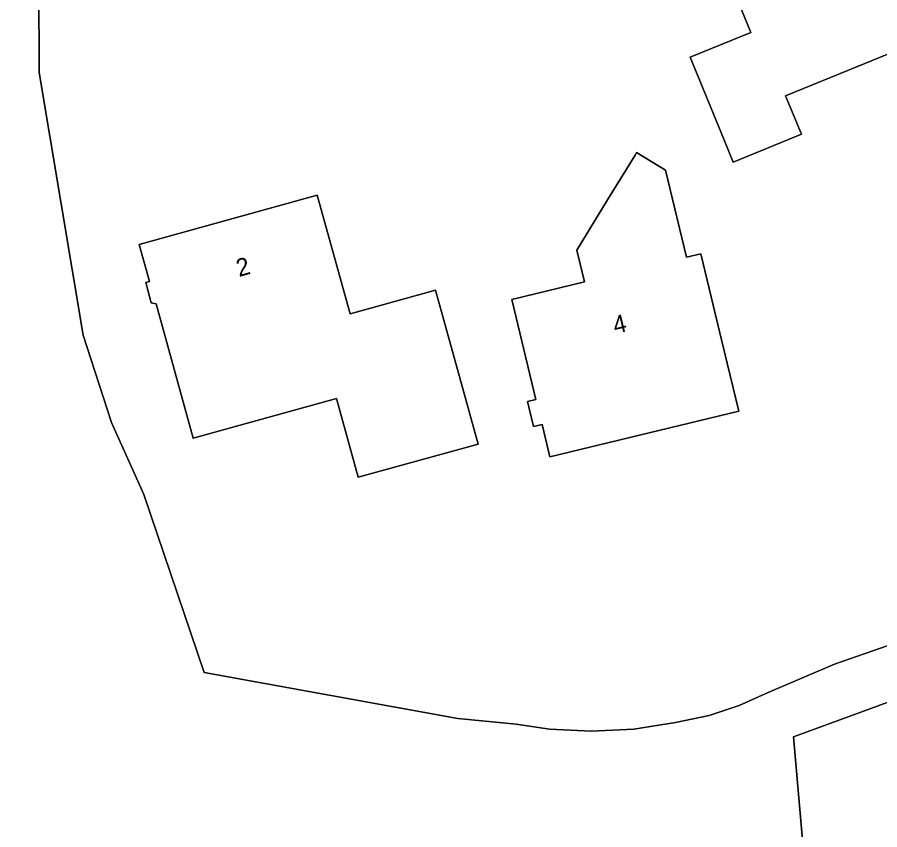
# Model space of a CAD drawing. Extents: x 162156 to 163172, y 378995 to 380779.
# Drawn here: x 162663.78 to 162712.54, y 380088.42 to 380134.38 of the extents above; entities that cross this region are included whole.
import ezdxf

# ---------------------------------------------------------------- set-up
doc = ezdxf.new("R2010")
doc.units = 0
for name, color, linetype in [('IMGEO_Erf', 7, 'Continuous'), ('IMGEO_Naaldbos', 7, 'Continuous'), ('IMGEO_Pand', 7, 'Continuous'), ('IMGEO_Pand_nummerreeks', 7, 'Continuous')]:
    doc.layers.add(name, color=color, linetype=linetype)

msp = doc.modelspace()

# ---------------------------------------------------------------- linework, layer by layer
at = {"layer": 'IMGEO_Erf'}
for points in [[(162714.758, 380133.013), (162707.223, 380129.931), (162708.11, 380127.761), (162704.256, 380126.184), (162703.725, 380127.483), (162701.832, 380132.11), (162705.263, 380133.513), (162704.065, 380136.442), (162715.035, 380140.929)], [(162666.225, 380138.522), (162664.994, 380136.169), (162665.017, 380131.245), (162667.515, 380116.396), (162669.104, 380111.454), (162670.935, 380107.393), (162674.348, 380097.308), (162688.685, 380094.714), (162691.981, 380094.399), (162693.865, 380094.119), (162696.25, 380093.992), (162698.635, 380094.115), (162700.994, 380094.486), (162702.891, 380094.89), (162704.592, 380095.451), (162706.226, 380096.187), (162709.98, 380097.788), (162714.749, 380099.439), (162731.647, 380103.299)], [(162729.408, 380100.063), (162720.422, 380098.094), (162713.945, 380095.981), (162707.667, 380093.669), (162709.547, 380072.093), (162684.738, 380059.133), (162663.781, 380052.371)]]:
    msp.add_lwpolyline(points, dxfattribs=at)
for points in [[(162704.575, 380112.089), (162693.9, 380109.519), (162693.449, 380111.351), (162692.959, 380111.234), (162692.619, 380112.647), (162693.096, 380112.762), (162691.736, 380118.417), (162695.852, 380119.408), (162695.42, 380121.203), (162697.16, 380124.045), (162698.706, 380126.569), (162698.799, 380126.722), (162700.424, 380125.727), (162701.609, 380120.802), (162702.431, 380121), (162703.601, 380116.139)], [(162688.765, 380114.115), (162689.834, 380110.238), (162683.058, 380108.37), (162681.834, 380112.808), (162673.727, 380110.572), (162671.635, 380118.159), (162671.36, 380118.231), (162671.044, 380119.375), (162671.252, 380119.433), (162670.674, 380121.53), (162680.744, 380124.307), (162682.594, 380117.6), (162687.436, 380118.935)]]:
    msp.add_lwpolyline(points, close=True, dxfattribs=at)
at = {"layer": 'IMGEO_Naaldbos'}
for points in [[(162707.667, 380093.669), (162713.945, 380095.981), (162720.422, 380098.094), (162729.408, 380100.063), (162731.647, 380103.299), (162714.749, 380099.439), (162709.98, 380097.788), (162706.226, 380096.187), (162704.592, 380095.451), (162702.891, 380094.89), (162700.994, 380094.486), (162698.635, 380094.115), (162696.25, 380093.992), (162693.865, 380094.119), (162691.981, 380094.399), (162688.685, 380094.714), (162674.348, 380097.308), (162670.935, 380107.393), (162669.104, 380111.454), (162667.515, 380116.396), (162665.017, 380131.245), (162664.994, 380136.169), (162666.225, 380138.522), (162664.523, 380139.522)], [(162663.781, 380052.371), (162684.738, 380059.133), (162709.547, 380072.093), (162707.667, 380093.669)]]:
    msp.add_lwpolyline(points, dxfattribs=at)
at = {"layer": 'IMGEO_Pand'}
for points in [[(162714.758, 380133.013), (162717.348, 380126.682), (162718.312, 380127.077), (162718.738, 380127.251), (162721.278, 380128.29), (162723.365, 380129.143), (162719.226, 380139.263), (162716.219, 380138.033), (162715.035, 380140.929), (162704.065, 380136.442), (162705.263, 380133.513), (162701.832, 380132.11), (162703.725, 380127.483), (162704.256, 380126.184), (162708.11, 380127.761), (162707.223, 380129.931)], [(162698.706, 380126.569), (162697.16, 380124.045), (162695.42, 380121.203), (162695.852, 380119.408), (162691.736, 380118.417), (162693.096, 380112.762), (162692.619, 380112.647), (162692.959, 380111.234), (162693.449, 380111.351), (162693.9, 380109.519), (162704.575, 380112.089), (162703.601, 380116.139), (162702.431, 380121), (162701.609, 380120.802), (162700.424, 380125.727), (162698.799, 380126.722)], [(162688.765, 380114.115), (162687.436, 380118.935), (162682.594, 380117.6), (162680.744, 380124.307), (162670.674, 380121.53), (162671.252, 380119.433), (162671.044, 380119.375), (162671.36, 380118.231), (162671.635, 380118.159), (162673.727, 380110.572), (162681.834, 380112.808), (162683.058, 380108.37), (162689.834, 380110.238)]]:
    msp.add_lwpolyline(points, close=True, dxfattribs=at)

# ---------------------------------------------------------------- texts
at = {"layer": 'IMGEO_Pand_nummerreeks'}
for s, rotation, p in [('2', 15.4172, (162676.314, 380119.683)), ('4', 13.5778, (162697.586, 380116.456))]:
    msp.add_text(s, height=1, rotation=rotation, dxfattribs=at).set_placement(p)

doc.saveas('drawing.dxf')
